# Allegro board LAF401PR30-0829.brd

Outline 328.05 x 120.8 mm; copper layers: TOP, GND1, IN1, GND2, IN2, IN3, VCC, IN4, GND3, BOTTOM. Coordinates in mm from the lower left corner of the outline.

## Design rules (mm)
net group 12: nets H_THERMTRIP# H_VCCST_PWRGD_XDP
net group 15: nets DDR_XDP_WAN_SMBDAT ESPI_CLK_5105
net group CLK_ITPXDP_: nets CLK_ITPXDP_N CLK_ITPXDP_P
net group CPU_DP2_0_C: nets CPU_DP2_N0_C CPU_DP2_P0_C
net group CPU_DP2_1_C: nets CPU_DP2_N1_C CPU_DP2_P1_C
net group CPU_DP2_2_C: nets CPU_DP2_N2_C CPU_DP2_P2_C
net group CPU_DP2_3_C: nets CPU_DP2_N3_C CPU_DP2_P3_C
net group CPU_DP2_AUX_C: nets CPU_DP2_AUXN_C CPU_DP2_AUXP_C
net group CPU_DP3_AUX: nets CPU_DP3_AUXN CPU_DP3_AUXP
net group CRT_CTL_5_10: nets CLK_DDC2_CRT DAT_DDC2_CRT
net group DDR_A_0: nets DDR_A_DQS0 DDR_A_DQS#0
net group DDR_A_1: nets DDR_A_DQS1 DDR_A_DQS#1
net group DDR_A_2: nets DDR_A_DQS2 DDR_A_DQS#2
net group DDR_A_3: nets DDR_A_DQS3 DDR_A_DQS#3
net group DDR_A_4: nets DDR_A_DQS4 DDR_A_DQS#4
net group DDR_A_5: nets DDR_A_DQS5 DDR_A_DQS#5
net group DDR_A_6: nets DDR_A_DQS6 DDR_A_DQS#6
net group DDR_A_7: nets DDR_A_DQS7 DDR_A_DQS#7
net group DDR_A_CLK0: nets DDR_A_CLK0 DDR_A_CLK#0
net group DDR_A_CLK1: nets DDR_A_CLK1 DDR_A_CLK#1
net group DDR_B_0: nets DDR_B_DQS0 DDR_B_DQS#0
net group DDR_B_1: nets DDR_B_DQS1 DDR_B_DQS#1
net group DDR_B_2: nets DDR_B_DQS2 DDR_B_DQS#2
net group DDR_B_3: nets DDR_B_DQS3 DDR_B_DQS#3
net group DDR_B_4: nets DDR_B_DQS4 DDR_B_DQS#4
net group DDR_B_5: nets DDR_B_DQS5 DDR_B_DQS#5
net group DDR_B_6: nets DDR_B_DQS6 DDR_B_DQS#6
net group DDR_B_7: nets DDR_B_DQS7 DDR_B_DQS#7
net group DDR_B_CLK0: nets DDR_B_CLK0 DDR_B_CLK#0
net group DDR_B_CLK1: nets DDR_B_CLK1 DDR_B_CLK#1
net group DIFFPAIR0: nets SML0_SMBCLK SML0_SMBDATA
net group DIFFPAIR2: nets CLK_TP_SIO_I2C_DAT DAT_TP_SIO_I2C_CLK
net group DIFFPAIR3: nets I2C1_SCK_TP I2C1_SDA_TP
net group DIFFPAIR4: nets I2C1_SCK_TP_R I2C1_SDA_TP_R
net group DIFFPAIR5: nets CLK_TP_SIO_R DAT_TP_SIO_R
net group DIFFPAIR12: nets ISH_I2C2_SCL_R ISH_I2C2_SDA_R
net group DIFFPAIR13: nets ISH_I2C2_SCL ISH_I2C2_SDA
net group DIFFPAIR14: nets ISPSCL ISPSDA
net group DIFFPAIR18: nets PCH_CL_CLK1 PCH_CL_DATA1
net group DIFFPAIR19: nets UIM_CLK UIM_DATA
net group DIFFPAIR21: nets MUX1_DP_SEL MUX1_USB_SEL
net group DIFFPAIR22: nets UPD1_SMBCLK_Q UPD1_SMBDAT_Q
net group DIFFPAIR31: nets UPD1_SMBCLK UPD1_SMBDAT
net group DIFFPAIR36: nets VCCIO_SENSE VSSIO_SENSE
net group DIFFPAIR37: nets UPD2_SMBCLK UPD2_SMBDAT
net group DIFFPAIR45: nets TUSB546A_SBU1_R TUSB546A_SBU2_R
net group DIFFPAIR46: nets TBTA_SBU1_R TBTA_SBU2_R
net group DIFFPAIR49: nets VCCSENSE VSSSENSE
net group DIFFPAIR50: nets VCC_GT_SENSE VSS_GT_SENSE
net group DP: nets CPU_DP1_AUXN CPU_DP1_AUXP
net group EDP_AUX_C: nets EDP_AUXN_C EDP_AUXP_C
net group EDP_TX0_C: nets EDP_TXN0_C EDP_TXP0_C
net group EDP_TX1_C: nets EDP_TXN1_C EDP_TXP1_C
net group HDA: nets HDA_BIT_CLK HDA_BIT_CLK_R
net group HDMI: nets CPU_DP2_CTRL_CLK CPU_DP2_CTRL_DATA
net group HDMI-CTL: nets HDMI_CTRL_CLK HDMI_CTRL_DATA
net group HDMI_CLK: nets HDMI_CLKN HDMI_CLKP
net group HDMI_L_CLK: nets HDMI_L_CLKN HDMI_L_CLKP
net group HDMI_L_TX_0: nets HDMI_L_TX_N0 HDMI_L_TX_P0
net group HDMI_L_TX_1: nets HDMI_L_TX_N1 HDMI_L_TX_P1
net group HDMI_L_TX_2: nets HDMI_L_TX_N2 HDMI_L_TX_P2
net group HDMI_TX_0: nets HDMI_TX_N0 HDMI_TX_P0
net group HDMI_TX_1: nets HDMI_TX_N1 HDMI_TX_P1
net group HDMI_TX_2: nets HDMI_TX_N2 HDMI_TX_P2
net group LAN_MDI0: nets LAN_MDIN0 LAN_MDIP0
net group LAN_MDI0_L: nets LAN_MDIN0_L LAN_MDIP0_L
net group LAN_MDI1: nets LAN_MDIN1 LAN_MDIP1
net group LAN_MDI1_L: nets LAN_MDIN1_L LAN_MDIP1_L
net group LAN_MDI2: nets LAN_MDIN2 LAN_MDIP2
net group LAN_MDI2_L: nets LAN_MDIN2_L LAN_MDIP2_L
net group LAN_MDI3: nets LAN_MDIN3 LAN_MDIP3
net group LAN_MDI3_L: nets LAN_MDIN3_L LAN_MDIP3_L
net group PCIE_PRX_C_DTX_4: nets PCIE_PRX_C_DTX_N4 PCIE_PRX_C_DTX_P4
net group PCIE_PRX_DTX_4: nets PCIE_PRX_DTX_N4 PCIE_PRX_DTX_P4
net group PCIE_PTX_C_DRX_4: nets PCIE_PTX_C_DRX_N4 PCIE_PTX_C_DRX_P4
net group PCIE_PTX_DRX_4: nets PCIE_PTX_DRX_N4 PCIE_PTX_DRX_P4
net group PCIE_RCOMP: nets PCIE_RCOMPN PCIE_RCOMPP
net group REM_DIODE1_: nets REM_DIODE1_N REM_DIODE1_P
net group REM_DIODE2_: nets REM_DIODE2_N REM_DIODE2_P
net group REM_DIODE4_: nets REM_DIODE4_N REM_DIODE4_P
net group RJ45_MDI0: nets RJ45_MDIN0 RJ45_MDIP0
net group RJ45_MDI1: nets RJ45_MDIN1 RJ45_MDIP1
net group RJ45_MDI2: nets RJ45_MDIN2 RJ45_MDIP2
net group RJ45_MDI3: nets RJ45_MDIN3 RJ45_MDIP3
net group SD/MMCDAT1/RCLK-: nets SD/MMCDAT0/RCLK+ SD/MMCDAT1/RCLK-
net group SD/MMCDAT1/RCLK-_R: nets SD/MMCDAT0/RCLK+_R SD/MMCDAT1/RCLK-_R
net group SD_UHS2_D0: nets SD_UHS2_D0N SD_UHS2_D0P
net group SD_UHS2_D1: nets SD_UHS2_D1N SD_UHS2_D1P
net group SW2_DP1_0_C: nets SW2_DP1_N0_C SW2_DP1_P0_C
net group SW2_DP1_1_C: nets SW2_DP1_N1_C SW2_DP1_P1_C
net group SW2_DP1_2_C: nets SW2_DP1_N2_C SW2_DP1_P2_C
net group SW2_DP1_3_C: nets SW2_DP1_N3_C SW2_DP1_P3_C
net group SW2_DP1_AUX_C: nets SW2_DP1_AUXN_C SW2_DP1_AUXP_C
net group SW2_DP3_0_C: nets SW2_DP3_N0_C SW2_DP3_P0_C
net group SW2_DP3_1_C: nets SW2_DP3_N1_C SW2_DP3_P1_C
net group SW2_DP3_AUX_C: nets SW2_DP3_AUXN_C SW2_DP3_AUXP_C
net group TBTA_SBU: nets TBTA_SBU1 TBTA_SBU2
net group THERMAL: nets POWER_SW#_MB POWER_SW_IN#
net group USB3_PRX_C_RD_DTX_6: nets USB3_PRX_C_RD_DTX_N6 USB3_PRX_C_RD_DTX_P6
net group USB3_PRX_L_DTX_2: nets USB3_PRX_L_DTX_N2 USB3_PRX_L_DTX_P2
net group USB3_PRX_RD_DTX_6: nets USB3_PRX_RD_DTX_N6 USB3_PRX_RD_DTX_P6
net group USB3_PTX_C_DRX_1: nets USB3_PTX_C_DRX_N1 USB3_PTX_C_DRX_P1
net group USB3_PTX_C_DRX_2: nets USB3_PTX_C_DRX_N2 USB3_PTX_C_DRX_P2
net group USB3_PTX_C_DRX_3: nets USB3_PTX_C_DRX_N3 USB3_PTX_C_DRX_P3
net group USB3_PTX_C_DRX_4: nets USB3_PTX_C_DRX_N4 USB3_PTX_C_DRX_P4
net group USB3_PTX_C_RD_DRX_6: nets USB3_PTX_C_RD_DRX_N6 USB3_PTX_C_RD_DRX_P6
net group USB3_PTX_L_DRX_2: nets USB3_PTX_L_DRX_N2 USB3_PTX_L_DRX_P2
net group USB3_PTX_RD_DRX_6: nets USB3_PTX_RD_DRX_N6 USB3_PTX_RD_DRX_P6
net group USB20_2_R: nets USB20_N2_R USB20_P2_R
net group USB20_3_R: nets USB20_N3_R USB20_P3_R
net group USB20_4_L: nets USB20_N4_L USB20_P4_L
net group USB20_5_R: nets USB20_N5_R USB20_P5_R
net group USB20_7_L: nets USB20_N7_L USB20_P7_L
net group USB20_8_R: nets USB20_N8_R USB20_P8_R
net group 20: nets +DDR_VREF_A_DQ +DDR_VREF_B_CA +DDR_VREF_B_DQ +DDR_VREF_CA DDR_DRAMRST# DDR_DRAMRST#_R INT_SPK_L+ INT_SPK_L- INT_SPK_R+ INT_SPK_R- INT_SPKR_L+ INT_SPKR_L- INT_SPKR_R+ INT_SPKR_R- SYS_RESET#
net group 5225: nets CAM_MIC_CBL_DET# CLK_ITPXDP_N_R CLK_ITPXDP_P_R CLK_PCIE_N0 CLK_PCIE_N1 CLK_PCIE_N3 CLK_PCIE_N4 CLK_PCIE_N5 CLK_PCIE_P0 CLK_PCIE_P1 CLK_PCIE_P3 CLK_PCIE_P4 CLK_PCIE_P5 CPU_DP1_CTRL_CLK CPU_DP1_CTRL_DATA CPU_DP1_N0 CPU_DP1_N1 CPU_DP1_N2 CPU_DP1_N3 CPU_DP1_P0 CPU_DP1_P1 CPU_DP1_P2 CPU_DP1_P3 CPU_DP2_AUXN CPU_DP2_AUXP CPU_DP2_N0 CPU_DP2_N1 CPU_DP2_N2 CPU_DP2_N3 CPU_DP2_P0 CPU_DP2_P1 CPU_DP2_P2 CPU_DP2_P3 EDP_AUXN EDP_AUXP EDP_BIA_PWM EDP_HPD EDP_TXN0 EDP_TXN1 EDP_TXP0 EDP_TXP1 ENVDD_PCH LPSS_UART2_RXD LPSS_UART2_TXD PANEL_BKLEN PCIE_PRX_DTX_N1 PCIE_PRX_DTX_N3 PCIE_PRX_DTX_N11 PCIE_PRX_DTX_N12 PCIE_PRX_DTX_P1 PCIE_PRX_DTX_P3 PCIE_PRX_DTX_P11 PCIE_PRX_DTX_P12 PCIE_PRX_RD_DTX_N11 PCIE_PRX_RD_DTX_N12 PCIE_PRX_RD_DTX_P11 PCIE_PRX_RD_DTX_P12 PCIE_PTX_DRX_N1 PCIE_PTX_DRX_N3 PCIE_PTX_DRX_N8 PCIE_PTX_DRX_N11 PCIE_PTX_DRX_N12 PCIE_PTX_DRX_P1 PCIE_PTX_DRX_P3 PCIE_PTX_DRX_P8 PCIE_PTX_DRX_P11 PCIE_PTX_DRX_P12 PCIE_PTX_RD_DRX_N11 PCIE_PTX_RD_DRX_P11 SATA_PRX_DTX_N0 SATA_PRX_DTX_P0 SW2_DP1_AUXN SW2_DP1_AUXP SW2_DP1_N0 SW2_DP1_N1 SW2_DP1_N2 SW2_DP1_N3 SW2_DP1_P0 SW2_DP1_P1 SW2_DP1_P2 SW2_DP1_P3 SW2_DP3_AUXN SW2_DP3_AUXP SW2_DP3_N0 SW2_DP3_N1 SW2_DP3_P0 SW2_DP3_P1 USB3_PRX_DTX_N2 USB3_PRX_DTX_N3 USB3_PRX_DTX_N4 USB3_PRX_DTX_P2 USB3_PRX_DTX_P3 USB3_PRX_DTX_P4 USB3_PTX_DRX_N1 USB3_PTX_DRX_N2 USB3_PTX_DRX_N3 USB3_PTX_DRX_N4 USB3_PTX_DRX_P1 USB3_PTX_DRX_P2 USB3_PTX_DRX_P3 USB3_PTX_DRX_P4 USB20_N2 USB20_N3 USB20_N4 USB20_N5 USB20_N7 USB20_N8 USB20_N9 USB20_N10 USB20_P2 USB20_P3 USB20_P4 USB20_P5 USB20_P7 USB20_P8 USB20_P9 USB20_P10
net group ADUIO: nets RING2 RING2_R SLEEVE SLEEVE_R
net group AUDIO: nets +LINE1-VREFO-L +LINE1-VREFO-R AUD_HP_NB_SENSE AUD_HP_OUT_L AUD_HP_OUT_L1 AUD_HP_OUT_R AUD_HP_OUT_R1 AUD_SENSE_A HP_OUT_L HP_OUT_R LINE1_L LINE1_R
net group B+: nets +PWR_SRC
net group CARD_READER: nets SD/MMCCD# SD/MMCCLK SD/MMCCLK_R SD/MMCCMD SD/MMCCMD_R SD/MMCDAT2 SD/MMCDAT2_R SD/MMCDAT3 SD/MMCDAT3_R SD_GPIO SDWP SDWP_Q
net group CLK: nets CLKREQ_PCIE#0 CLKREQ_PCIE#1 CLKREQ_PCIE#3 CLKREQ_PCIE#4 CLKREQ_PCIE#5 CPU_XDP_TCLK JTAG_CLK MEC_XTAL1 MEC_XTAL2 MEC_XTAL2_R MSCLK PCH_JTAG_TCK PCI_CLK_LPC1 SUSCLK SUSCLK_R WIGIG_32KHZ XDP_JTAGX XTALI XTALO XTALO_R
net group CPU: nets H_CATERR# PCH_PLTRST# PCH_PLTRST#_5105 PCH_PLTRST#_AND PCH_PLTRST#_EC PLTRST_LAN# PLTRST_TPM# VCCST_PWRGD XDP_OBS0 XDP_OBS0_R XDP_OBS1 XDP_OBS1_R
net group CRITICAL: nets INTRUDER# PCH_DPWROK PCH_PCIE_WAKE# PCH_RSMRST# PCIE_WAKE# PCIE_WAKE#_R RESET_OUT#_R SIO_PWRBTN# SRTCRST# SYS_RESET#_R
net group CRT_DAC_20_30: nets BLUE BLUE_CRT GREEN GREEN_CRT RED RED_CRT
net group CRT_SYNC_12_20: nets HSYNC_CONN HSYNC_CRT VSYNC_CONN VSYNC_CRT
net group CTL-LINK: nets PCH_CL_RST1#
net group DDRADD_ALERT_10/11_19/20_25: nets DDR_A_ACT# DDR_A_ALERT# DDR_A_BA0 DDR_A_BA1 DDR_A_BG0 DDR_A_BG1 DDR_A_MA0 DDR_A_MA1 DDR_A_MA2 DDR_A_MA3 DDR_A_MA4 DDR_A_MA5 DDR_A_MA6 DDR_A_MA7 DDR_A_MA8 DDR_A_MA9 DDR_A_MA10 DDR_A_MA11 DDR_A_MA12 DDR_A_MA13 DDR_A_MA14 DDR_A_MA15 DDR_A_MA16 DDR_A_PARITY DDR_B_ACT# DDR_B_ALERT# DDR_B_BA0 DDR_B_BA1 DDR_B_BG0 DDR_B_BG1 DDR_B_MA0 DDR_B_MA1 DDR_B_MA2 DDR_B_MA3 DDR_B_MA4 DDR_B_MA5 DDR_B_MA6 DDR_B_MA7 DDR_B_MA8 DDR_B_MA9 DDR_B_MA10 DDR_B_MA11 DDR_B_MA12 DDR_B_MA13 DDR_B_MA14 DDR_B_MA15 DDR_B_MA16 DDR_B_PARITY
net group DDRCTL_CKE_10/11_19/20_25: nets DDR_A_CKE0 DDR_A_CKE1 DDR_A_CS#0 DDR_A_CS#1 DDR_A_ODT0 DDR_A_ODT1 DDR_B_CKE0 DDR_B_CKE1 DDR_B_CS#0 DDR_B_CS#1 DDR_B_ODT0 DDR_B_ODT1
net group DDRD0_19/8.5/10_19/20_25: nets DDR_A_D0 DDR_A_D1 DDR_A_D2 DDR_A_D3 DDR_A_D4 DDR_A_D5 DDR_A_D6 DDR_A_D7 DDR_A_D16 DDR_A_D17 DDR_A_D18 DDR_A_D19 DDR_A_D20 DDR_A_D21 DDR_A_D22 DDR_A_D23 DDR_A_D32 DDR_A_D33 DDR_A_D34 DDR_A_D35 DDR_A_D36 DDR_A_D37 DDR_A_D38 DDR_A_D39 DDR_A_D48 DDR_A_D49 DDR_A_D50 DDR_A_D51 DDR_A_D52 DDR_A_D53 DDR_A_D54 DDR_A_D55 DDR_B_D0 DDR_B_D1 DDR_B_D2 DDR_B_D3 DDR_B_D4 DDR_B_D5 DDR_B_D6 DDR_B_D7 DDR_B_D16 DDR_B_D17 DDR_B_D18 DDR_B_D19 DDR_B_D20 DDR_B_D21 DDR_B_D22 DDR_B_D23 DDR_B_D32 DDR_B_D33 DDR_B_D34 DDR_B_D35 DDR_B_D36 DDR_B_D37 DDR_B_D38 DDR_B_D39 DDR_B_D48 DDR_B_D49 DDR_B_D50 DDR_B_D51 DDR_B_D52 DDR_B_D53 DDR_B_D54 DDR_B_D55
net group DDRD1_19/8.5/10_19/20_25: nets DDR_A_D8 DDR_A_D9 DDR_A_D10 DDR_A_D11 DDR_A_D12 DDR_A_D13 DDR_A_D14 DDR_A_D15 DDR_A_D24 DDR_A_D25 DDR_A_D26 DDR_A_D27 DDR_A_D28 DDR_A_D29 DDR_A_D30 DDR_A_D31 DDR_A_D40 DDR_A_D41 DDR_A_D42 DDR_A_D43 DDR_A_D44 DDR_A_D45 DDR_A_D46 DDR_A_D47 DDR_A_D56 DDR_A_D57 DDR_A_D58 DDR_A_D59 DDR_A_D60 DDR_A_D61 DDR_A_D62 DDR_A_D63 DDR_B_D8 DDR_B_D9 DDR_B_D10 DDR_B_D11 DDR_B_D12 DDR_B_D13 DDR_B_D14 DDR_B_D15 DDR_B_D24 DDR_B_D25 DDR_B_D26 DDR_B_D27 DDR_B_D28 DDR_B_D29 DDR_B_D30 DDR_B_D31 DDR_B_D40 DDR_B_D41 DDR_B_D42 DDR_B_D43 DDR_B_D44 DDR_B_D45 DDR_B_D46 DDR_B_D47 DDR_B_D56 DDR_B_D57 DDR_B_D58 DDR_B_D59 DDR_B_D60 DDR_B_D61 DDR_B_D62 DDR_B_D63
net group DIFFPAIR1: nets SML1_SMBCLK
net group DIFFPAIR8: nets DDR_XDP_WAN_SMBCLK
net group DIFFPAIR15: nets MEM_SMBCLK
net group DIFFPAIR16: nets PBAT_CHARGER_SMBCLK
net group DIFFPAIR17: nets PBAT_SMBCLK_C
net group DMIC: nets DMIC0 DMIC_CLK0 DMIC_CLK_CODEC
net group ESPI: nets ESPI_CS# ESPI_IO0 ESPI_IO0_R ESPI_IO1 ESPI_IO1_R ESPI_IO2 ESPI_IO2_R ESPI_IO3 ESPI_IO3_R
net group HDA_5_15: nets HDA_RST# HDA_RST#_R HDA_SDIN0 HDA_SDIN0_R HDA_SDOUT HDA_SDOUT_R HDA_SYNC HDA_SYNC_R
net group PCIE: nets PCIE_PRX_C_DTX_N1 PCIE_PRX_C_DTX_N11 PCIE_PRX_C_DTX_N12 PCIE_PRX_C_DTX_P1 PCIE_PRX_C_DTX_P11 PCIE_PRX_C_DTX_P12 PCIE_PRX_C_RD_DTX_N8 PCIE_PRX_C_RD_DTX_N11 PCIE_PRX_C_RD_DTX_N12 PCIE_PRX_C_RD_DTX_P8 PCIE_PRX_C_RD_DTX_P11 PCIE_PRX_C_RD_DTX_P12 PCIE_PRX_DTX_N8 PCIE_PRX_DTX_P8 PCIE_PRX_RD_DTX_N8 PCIE_PRX_RD_DTX_P8 PCIE_PTX_C_DRX_N1 PCIE_PTX_C_DRX_N3 PCIE_PTX_C_DRX_N8 PCIE_PTX_C_DRX_N11 PCIE_PTX_C_DRX_N12 PCIE_PTX_C_DRX_P1 PCIE_PTX_C_DRX_P3 PCIE_PTX_C_DRX_P8 PCIE_PTX_C_DRX_P11 PCIE_PTX_C_DRX_P12 PCIE_PTX_C_RD_DRX_N8 PCIE_PTX_C_RD_DRX_N11 PCIE_PTX_C_RD_DRX_N12 PCIE_PTX_C_RD_DRX_P8 PCIE_PTX_C_RD_DRX_P11 PCIE_PTX_C_RD_DRX_P12 PCIE_PTX_RD_DRX_N8 PCIE_PTX_RD_DRX_N12 PCIE_PTX_RD_DRX_P8 PCIE_PTX_RD_DRX_P12
net group POWER: nets +1.2V_MEM
net group RCOMP: nets CFG_RCOMP CPU_POPIRCOMP EDP_COMP EDRAM_OPIO_RCOMP EMMC_RCOMP EOPIO_RCOMP PCH_POPIRCOMP SD_RCOMP SM_RCOMP0 SM_RCOMP1 SM_RCOMP2 USBCOMP
net group RTC: nets PCH_RTCRST# PCH_RTCX1 PCH_RTCX2 PCH_RTCX2_R
net group SATA: nets SATA_PRX_C_DTX_N0 SATA_PRX_C_DTX_P0 SATA_PRX_C_RD_DTX_N0 SATA_PRX_C_RD_DTX_P0 SATA_PRX_RD_DTX_N0 SATA_PRX_RD_DTX_P0 SATA_PTX_C_DRX_N0 SATA_PTX_C_DRX_P0 SATA_PTX_C_RD_DRX_N0 SATA_PTX_C_RD_DRX_P0 SATA_PTX_DRX_N0 SATA_PTX_DRX_P0 SATA_PTX_RD_DRX_N0 SATA_PTX_RD_DRX_P0
net group SMBUS: nets GPP_C5 MEM_SMBDATA PBAT_CHARGER_SMBDAT PBAT_SMBDAT_C PCH_SMB_ALERT# SML1_SMBDATA
net group SPI: nets PCH_SPI_CLK PCH_SPI_CLK_0_R PCH_SPI_CLK_1_R PCH_SPI_CLK_2_R PCH_SPI_CLK_R1 PCH_SPI_CS#0 PCH_SPI_CS#0_R1 PCH_SPI_CS#0_R2 PCH_SPI_CS#1 PCH_SPI_CS#1_R1 PCH_SPI_CS#1_R2 PCH_SPI_CS#2 PCH_SPI_CS#2_R PCH_SPI_D0 PCH_SPI_D0_0_R PCH_SPI_D0_1_R PCH_SPI_D0_2_R PCH_SPI_D0_R1 PCH_SPI_D1 PCH_SPI_D1_0_R PCH_SPI_D1_1_R PCH_SPI_D1_2_R PCH_SPI_D1_R1 PCH_SPI_D2 PCH_SPI_D2_0_R PCH_SPI_D2_1_R PCH_SPI_D2_R1 PCH_SPI_D3 PCH_SPI_D3_0_R PCH_SPI_D3_1_R PCH_SPI_D3_R1 PCH_SPI_DO2_XDP PCH_SPI_DO_XDP TBTA_ROM_CLK_PD TBTA_ROM_CLK_PD_R TBTA_ROM_CS#_PD TBTA_ROM_CS#_PD_R TBTA_ROM_DI_PD TBTA_ROM_DI_PD_R TBTA_ROM_DO_PD TBTA_ROM_DO_PD_R
net group SVID: nets H_CPU_SVIDALRT# PECI_EC PECI_EC_R VIDALERT_N VIDALERT_N_B VIDSCLK VIDSCLK_B VIDSOUT VIDSOUT_B
net group TBTA-USB30: nets TBTA_AUXN_C TBTA_AUXP_C TBTA_BOT_N TBTA_BOT_N_R TBTA_BOT_P TBTA_BOT_P_R TBTA_RX1N TBTA_RX1P TBTA_RX2N TBTA_RX2P TBTA_TOP_N TBTA_TOP_N_R TBTA_TOP_P TBTA_TOP_P_R TBTA_TX1N TBTA_TX1N_C TBTA_TX1P TBTA_TX1P_C TBTA_TX2N TBTA_TX2N_C TBTA_TX2P TBTA_TX2P_C
net group UIM: nets UIM_RESET
net group USB20: nets SW_USB20_N9 SW_USB20_P9 USB20_N1 USB20_N9_R USB20_P1 USB20_P9_R
net group USB30: nets USB3_PRX_C_DTX_N1 USB3_PRX_C_DTX_P1 USB3_PRX_DTX_N1 USB3_PRX_DTX_N6 USB3_PRX_DTX_P1 USB3_PRX_DTX_P6 USB3_PTX_C_DRX_N6 USB3_PTX_C_DRX_P6 USB3_PTX_DRX_N6 USB3_PTX_DRX_P6
nets with their own width: min track width 0.254; nets +1.0VO_DSW +1.2V_MEM_CPUCLK +5V_ALW +VCC_GT_AK52 +VCC_GT_K52 AUD_PC_BEEP BAT1_LED# BAT2_LED# BATT_WHITE# BATT_YELLOW# BEEP_R N16400770 N18762401 N18762411 N18762416 N18762426 N18762428 N18762438 N20151644 N27077001 N132005053 SLP_WLAN#_M SPKR_R TBTA_CC1 VCC_GT VCC_IA1 VCC_IA2 WLAN_PWR_EN XCLK_BIASREF
nets with their own width: min track width 0.305; nets +RREF
nets with their own width: min track width 0.508; nets +1.0V_AMPHYPLL +1.0V_APLL +1.0V_APLLEBB +1.0V_CLK1 +1.0V_CLK2 +1.0V_CLK3 +1.0V_CLK4 +1.0V_CLK5 +1.0V_CLK6 +1.0V_DTS +1.0V_PRIM +1.0V_PRIM_XDP +1.0V_VCCST +1.0V_VCCST_C +1.0V_VCCSTG +1.0V_VCCSTG_C +1.2V_LDO +1.8V_PRIM +1.8V_RUN +1.8V_RUN_CARD +3.3V_1.8V_PGPPA +3.3V_1.8V_PGPPG +3.3V_ALW +3.3V_ALW2 +3.3V_ALW_DSW +3.3V_ALW_DSW_R +3.3V_ALW_PCH +3.3V_ALW_UE1 +3.3V_ALW_UZ12 +3.3V_CAM +3.3V_CPS +3.3V_LAN_OUT +3.3V_M_TPM +3.3V_MMI_AUX +3.3V_PGPPB +3.3V_PGPPC +3.3V_PGPPD +3.3V_PGPPE +3.3V_RTC_LDO +3.3V_RUN +3.3V_RUN_AUDIO +3.3V_RUN_AUDIO_DVDD +3.3V_RUN_AUDIO_IO +3.3V_RUN_AUDIO_UZ5 +3.3V_RUN_UT9 +3.3V_SPI +3.3V_TBTA_FLASH +3.3V_TP +3.3V_VCCHDA +5V_ALW2 +5V_RUN +5V_RUN_CHG +COINCELL +DC_IN_SS +DDR_VREF_A_CA +DV33_18 +GND_CHASSIS +MIC2-VREFO +RSVD_VCC3P3_1 +RTC_CELL +RTC_CELL_PCH +SDREG2 +UZ12_TPM +UZ12_VHIO +VBUS_DC_SS +VCC_1P8 +VCC_CORE +VCC_GT +VCC_SA +VCC_SFR_OC +VDD_DAC_33 +VDDA_AVDD1 +VSS_PLL +Z4012 GND GNDA GT_SNUB IA_SNUB1 IA_SW1
nets with their own width: min track width 0.762; nets +0.9V_LAN +1.0V_SRAM +2.5V_MEM +3.3V_VDD_PIC +3.3V_VDD_PIC_PDA +3.3V_VGA
nets with their own width: min track width 1.016; nets +0.6V_DDR_VTT +1.8V_PGPPF +1.8V_RUN_UZ8 +3.3V_ALW_PCH_UZ3 +3.3V_LAN +3.3V_LAN_UZ2 +3.3V_RUN_CARD +5V_TSP +CRT_VCC +VHDMI_VCC
nets with their own width: min track width 1.27; nets +3.3V_MMI_IN
nets with their own width: min track width 1.524; nets +5V_HDD +5V_HDD_UZ23 +EDP_VDD +LCDVDD
nets with their own width: min track width 2.032; nets +BL_PWR_SRC +USB_EX2_PWR +USB_EX3_PWR
nets with their own width: min track width 2.286; nets +3.3V_HDD +3.3V_WLAN +3.3V_WWAN_UZ2
nets with their own width: min track width 2.54; nets +5V_RUN_AUDIO +5V_RUN_AUDIO_UZ5 +5V_RUN_PVDD_L +5V_RUN_UZ4 +5V_USB_CHG_PWR
nets with their own width: min track width 2.794; nets +1.0V_PRIM_CORE +3.3V_WLAN_UZ4 +3.3V_WWAN
nets with their own width: min track width 3.048; nets +1.0V_MPHYAON +1.0V_MPHYGT +3.3V_HDD_M2
nets with their own width: min track width 3.302; nets +1.0VS_VCCIO
nets with their own width: min track width 3.556; nets +3.3V_RUN_UZ3 +5V_ALW_PDA

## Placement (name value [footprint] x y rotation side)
CA1  680P_0402_50V7K  [C_0402]  313.82 40.29 270 bottom
CA2  330P_0402_50V8J  [C_0402]  312.62 33.55 270 top
CA3  330P_0402_50V8J  [C_0402]  311.54 34.82 270 bottom
CA4  680P_0402_50V7K  [C_0402]  311.97 40.28 0 bottom
CA5  100P_0402_50V8J  [C_0402]  113.67 88.8 270 bottom
CA6  100P_0402_50V8J  [C_0402]  114.69 88.8 270 bottom
CA7  100P_0201_25V7K  [C_0201]  111.89 91.84 0 top
CA8  0.1U_0201_10V6K  [C_0201]  304.04 33.2 270 top
CA9  10U_0603_10V6M  [C_0603]  305.63 31.7 180 top
CA10  0.1U_0201_10V6K  [C_0201]  295.28 38.33 90 top
CA12  680P_0402_50V7K  [C_0402]  312.3 36.67 270 bottom
CA13  680P_0402_50V7K  [C_0402]  310.65 41.17 270 bottom
CA19  1000P_0402_50V7K  [C_0402]  297.69 39.21 270 bottom
CA22  1000P_0402_50V7K  [C_0402]  300.36 39.21 270 bottom
CA23  1000P_0402_50V7K  [C_0402]  299.47 39.21 270 bottom
CA24  1000P_0402_50V7K  [C_0402]  298.58 39.21 270 bottom
CA25  10U_0603_10V6M  [C_0603]  300.55 29.42 0 top
CA27  0.1U_0402_25V6  [C_0402]  299.65 29.93 180 top
CA28  0.1U_0402_25V6  [C_0402]  296.85 29.93 0 top
CA29  1U_0603_10V6K  [C_0603]  304.17 38.69 90 top
CA31  1U_0603_10V6K  [C_0603]  296.8 39.9 180 top
CA33  10P_0402_50V8J  [C_0402]  291.75 37.1 180 top
CA35  2.2U_0402_6.3V6M  [C_0402]  306.76 34.31 0 top
CA41  0.1U_0402_25V6  [C_0402]  295.34 30.83 270 top
CA43  10U_0603_10V6M  [C_0603]  305.63 30.12 0 top
CA44  10U_0603_10V6M  [C_0603]  303.28 30.12 0 top
CA45  0.1U_0201_10V6K  [C_0201]  300.14 41.29 180 top
CA46  10U_0603_10V6M  [C_0603]  300.23 42.18 180 top
CA47  0.1U_0201_10V6K  [C_0201]  298.04 41.29 0 top
CA48  10U_0603_10V6M  [C_0603]  298.84 44.73 180 top
CA49  1U_0603_10V6K  [C_0603]  305.44 38.69 90 top
CA51  10U_0603_10V6M  [C_0603]  306.58 33.23 0 top
CA52  10U_0603_10V6M  [C_0603]  304.17 41.1 90 top
CA53  10U_0603_10V6M  [C_0603]  294.14 36.02 180 top
CA54  27P_0402_50V8J  [C_0402]  291.75 37.99 180 top
CA55  0.1U_0201_10V6K  [C_0201]  295.28 33.77 270 top
CA56  10U_0603_10V6M  [C_0603]  294.52 33.8 180 top
CA57  0.1U_0201_10V6K  [C_0201]  301.4 40.21 0 top
CA58  10U_0603_10V6M  [C_0603]  301.44 41.42 0 top
CA59  10U_0603_10V6M  [C_0603]  310.08 27.89 0 top
CA60  0.1U_0201_10V6K  [C_0201]  306.84 27.67 90 top
CA61  10U_0603_10V6M  [C_0603]  293.76 39.92 180 top
CA62  100P_0402_50V8J  [C_0402]  296.8 29.05 270 top
CA63  12P_0402_50V8J  [C_0402]  276.74 68.29 270 top
CA64  68P_0402_50V8J  [C_0402]  275.72 68.29 270 top
CA65  12P_0402_50V8J  [C_0402]  272.62 45.99 180 top
CA66  68P_0402_50V8J  [C_0402]  272.62 45.1 180 top
CA67  12P_0402_50V8J  [C_0402]  272.42 78.5 90 top
CA68  68P_0402_50V8J  [C_0402]  271.53 78.5 90 top
CA69  33P_0402_50V8J  [C_0402]  302.27 37.31 270 bottom
CA72  100P_0402_50V8J  [C_0402]  299.6 28.67 270 top
CC7  33P_0402_50V8J  [C_0402]  150.42 53.83 0 bottom
CC8  33P_0402_50V8J  [C_0402]  151.14 63.95 90 bottom
CC9  0.1U_0201_10V6K  [C_0201]  152.02 66.95 270 bottom
CC10  0.1U_0201_10V6K  [C_0201]  151.14 58.57 180 bottom
CC21  12P_0402_50V8J  [C_0402]  116.6 80.27 180 bottom
CC22  12P_0402_50V8J  [C_0402]  117.47 80.27 0 bottom
CC23  12P_0402_50V8J  [C_0402]  149.61 42.18 180 bottom
CC26  12P_0402_50V8J  [C_0402]  152.41 43.58 180 bottom
CC27  47P_0402_50V8J  [C_0402]  127.02 35.51 180 top
CC28  0.1U_0201_10V6K  [C_0201]  64.9 27.68 270 top
CC29  0.1U_0201_10V6K  [C_0201]  64.14 38.52 90 top
CC30  0.1U_0201_10V6K  [C_0201]  56.01 32.25 270 top
CC32  0.1U_0402_25V6  [C_0402]  63.89 27.59 270 top
CC33  0.1U_0402_25V6  [C_0402]  62.36 38.36 90 top
CC78  1U_0201_6.3V6M  [C_0201]  135.06 39.78 270 top
CC79  1U_0201_6.3V6M  [C_0201]  134.45 39.78 270 top
CC80  1U_0201_6.3V6M  [C_0201]  153.93 52.36 270 bottom
CC81  1U_0201_6.3V6M  [C_0201]  153.34 52.36 270 bottom
CC84  1U_0201_6.3V6M  [C_0201]  121.15 64.92 180 top
CC85  1U_0201_6.3V6M  [C_0201]  121.15 65.5 180 top
CC86  1U_0201_6.3V6M  [C_0201]  128.95 64.74 180 top
CC87  1U_0201_6.3V6M  [C_0201]  128.43 64.14 270 top
CC88  1U_0201_6.3V6M  [C_0201]  131.98 54.11 270 top
CC89  1U_0201_6.3V6M  [C_0201]  133.16 53.76 180 top
CC90  1U_0201_6.3V6M  [C_0201]  126.89 56.86 180 top
CC91  1U_0201_6.3V6M  [C_0201]  126.89 57.45 180 top
CC92  1U_0201_6.3V6M  [C_0201]  128.39 61 0 top
CC93  1U_0201_6.3V6M  [C_0201]  128.39 61.59 0 top
CC94  1U_0201_6.3V6M  [C_0201]  128.64 58.31 180 top
CC95  1U_0201_6.3V6M  [C_0201]  128.64 57.73 180 top
CC96  1U_0201_6.3V6M  [C_0201]  127.45 59.12 180 top
CC97  1U_0201_6.3V6M  [C_0201]  127.45 58.54 180 top
CC98  1U_0201_6.3V6M  [C_0201]  156.2 67.43 0 top
CC99  1U_0201_6.3V6M  [C_0201]  156.2 66.85 0 top
CC100  1U_0201_6.3V6M  [C_0201]  148.4 60.7 0 top
CC101  1U_0201_6.3V6M  [C_0201]  148.4 60.09 0 top
CC102  1U_0201_6.3V6M  [C_0201]  127.02 55.16 0 top
CC103  1U_0201_6.3V6M  [C_0201]  127.02 55.75 0 top
CC104  1U_0201_6.3V6M  [C_0201]  127.89 33.3 270 top
CC105  1U_0201_6.3V6M  [C_0201]  127.32 33.3 270 top
CC106  1U_0201_6.3V6M  [C_0201]  137.69 84.3 0 top
CC107  1U_0201_6.3V6M  [C_0201]  137.69 84.93 0 top
CC108  1U_0201_6.3V6M  [C_0201]  125.47 58.23 180 top
CC109  1U_0201_6.3V6M  [C_0201]  125.47 57.65 180 top
CC110  1U_0201_6.3V6M  [C_0201]  144.84 74.02 90 top
CC111  1U_0201_6.3V6M  [C_0201]  144.25 74.02 90 top
CC112  1U_0201_6.3V6M  [C_0201]  130.14 59.57 0 top
CC113  1U_0201_6.3V6M  [C_0201]  129.48 59.57 180 top
CC118  1U_0201_6.3V6M  [C_0201]  120.06 55.89 90 top
CC119  1U_0201_6.3V6M  [C_0201]  119.49 55.89 90 top
CC122  1U_0201_6.3V6M  [C_0201]  118.23 53.43 180 top
CC123  1U_0201_6.3V6M  [C_0201]  118.23 54.04 180 top
CC124  1U_0201_6.3V6M  [C_0201]  128.9 56.61 180 top
CC125  1U_0201_6.3V6M  [C_0201]  128.9 56.03 180 top
CC126  1U_0201_6.3V6M  [C_0201]  150.54 57.88 0 bottom
CC127  1U_0201_6.3V6M  [C_0201]  150.54 57.3 0 bottom
CC128  1U_0201_6.3V6M  [C_0201]  147.9 68.85 0 top
CC129  1U_0201_6.3V6M  [C_0201]  147.9 69.44 0 top
CC176  10U_0402_6.3V6M  [C_0402]  115.32 42.19 270 top
CC177  10U_0402_6.3V6M  [C_0402]  112.91 41.93 90 top
CC178  10U_0402_6.3V6M  [C_0402]  118.75 38.5 90 top
CC179  10U_0402_6.3V6M  [C_0402]  103.15 38.34 90 top
CC195  1U_0402_6.3V6K  [C_0402]  124.47 63.77 180 top
CC202  1U_0402_6.3V6K  [C_0402]  124.27 80.19 180 top
CC210  47U_0805_6.3V6M  [C_0805]  155.33 65.68 0 top
CC214  0.1U_0201_10V6K  [C_0201]  139.2 39.77 270 top
CC219  22U_0603_6.3V6M  [C_0603]  147.48 70.33 0 top
CC220  22U_0603_6.3V6M  [C_0603]  126.77 80.31 90 top
CC221  22U_0603_6.3V6M  [C_0603]  135.01 84.51 90 top
CC223  0.1U_0201_10V6K  [C_0201]  131.13 56.46 180 top
CC224  1U_0402_6.3V6K  [C_0402]  131.98 55.47 90 top
CC225  12P_0402_50V8J  [C_0402]  144.53 65.3 0 top
CC226  22U_0603_6.3V6M  [C_0603]  124.3 80.56 180 bottom
CC250  1U_0402_6.3V6K  [C_0402]  120.79 55.28 90 top
CC252  1U_0402_6.3V6K  [C_0402]  119 54 270 top
CC266  0.01UF_0402_25V7K  [C_0402]  130.18 36.34 270 top
CC269  0.1U_0402_25V6  [C_0402]  65.92 38.36 90 top
CC270  0.1U_0201_10V6K  [C_0201]  126.43 53.14 180 top
CC279  22U_0603_6.3V6M  [C_0603]  175.14 31.01 270 top
CC280  22U_0603_6.3V6M  [C_0603]  176.34 31.01 270 top
CC281  0.1U_0201_10V6K  [C_0201]  156.2 68.01 0 top
CC288  1U_0402_6.3V6K  [C_0402]  121.54 28.97 90 top
CC294  22U_0603_6.3V6M  [C_0603]  111 42.18 270 top
CC295  22U_0603_6.3V6M  [C_0603]  120.53 37.1 90 top
CC296  22U_0603_6.3V6M  [C_0603]  120.53 41.55 270 top
CC297  10U_0402_6.3V6M  [C_0402]  114.06 53.87 180 top
CC300  100P_0402_50V8J  [C_0402]  91.25 80.24 90 bottom
CC301  100P_0402_50V8J  [C_0402]  96.65 77.12 270 bottom
CC302  0.1U_0402_25V6  [C_0402]  147.25 87.45 0 bottom
CC303  0.1U_0402_25V6  [C_0402]  105.8 75.44 90 bottom
CC304  0.1U_0402_25V6  [C_0402]  104.02 75.46 90 bottom
CC305  0.1U_0402_25V6  [C_0402]  102.75 75.44 90 bottom
CC306  0.1U_0402_25V6  [C_0402]  54.74 35.82 90 top
CC307  0.1U_0402_25V6  [C_0402]  66.93 38.36 90 top
CC308  0.1U_0402_25V6  [C_0402]  53.22 29.3 270 top
CC310  0.1U_0402_25V6  [C_0402]  94.62 79.9 90 bottom
CC312  0.1U_0402_25V6  [C_0402]  100.72 79 90 bottom
CC313  0.1U_0201_10V6K  [C_0201]  125.5 54.69 270 top
CC314  0.1U_0201_10V6K  [C_0201]  132.63 60.47 270 top
CC316  33P_0402_50V8J  [C_0402]  139.71 42.83 270 top
CC318  33P_0402_50V8J  [C_0402]  149.23 60.22 180 bottom
CC319  33P_0402_50V8J  [C_0402]  146.61 62.76 180 bottom
CC320  33P_0402_50V8J  [C_0402]  148.67 66.12 180 top
CC321  33P_0402_50V8J  [C_0402]  100.59 75.46 90 bottom
CC322  2.2P_0402_50V8C  [C_0402]  122.43 28.97 90 top
CC323  2.2P_0402_50V8C  [C_0402]  144.45 61.31 90 top
CC324  2.2P_0402_50V8C  [C_0402]  125.35 32.53 90 top
CC325  2.2P_0402_50V8C  [C_0402]  126.44 61.51 180 top
CC331  2.2P_0402_50V8C  [C_0402]  128.02 36.39 90 top
CC332  2.2P_0402_50V8C  [C_0402]  128.41 31.64 180 top
CC333  2.2P_0402_50V8C  [C_0402]  128.94 40.12 90 top
CC334  12P_0402_50V8J  [C_0402]  145.57 72.76 0 bottom
CC335  12P_0402_50V8J  [C_0402]  145.55 75.58 90 bottom
CC336  100P_0402_50V8J  [C_0402]  96.78 78.99 90 bottom
CC337  12P_0402_50V8J  [C_0402]  125.71 59.94 270 top
CC340  0.1U_0402_25V6K  [C_0402]  177.2 33.55 180 top
CC341  18P_0402_50V8J  [C_0402]  159.57 55.44 0 top
CD1  10U_0603_10V6M  [C_0603]  65.63 13.84 270 top
CD2  10U_0603_10V6M  [C_0603]  79.34 13.59 270 top
CD3  10U_0603_10V6M  [C_0603]  74.14 4.07 90 top
CD4  10U_0603_10V6M  [C_0603]  68.29 4.07 90 top
CD5  10U_0603_10V6M  [C_0603]  52.61 4.76 0 top
CD6  10U_0603_10V6M  [C_0603]  75.41 13.59 270 top
CD7  10U_0603_10V6M  [C_0603]  71.72 4.07 90 top
CD8  10U_0603_10V6M  [C_0603]  59.95 13.86 270 top
CD17  330U_D3_2.5VY_R6M  [C_D3]  85.63 13.12 90 top
CD20  10U_0603_10V6M  [C_0603]  109.06 10.42 90 top
CD21  10U_0603_10V6M  [C_0603]  107.79 10.42 90 top
CD22  10U_0603_10V6M  [C_0603]  106.81 3.95 270 top
CD25  0.1U_0402_10V6K  [C_0402]  81.92 5.24 270 top
CD26  2.2U_0402_6.3V6M  [C_0402]  82.94 5.24 270 top
CD27  2.2U_0402_6.3V6M  [C_0402]  104.82 8.95 180 top
CD28  0.1U_0201_10V6K  [C_0201]  104.65 9.72 180 top
CD29  0.1U_0402_25V6  [C_0402]  65.88 5.27 180 top
CD31  0.022U_0402_16V7K  [C_0402]  83.75 3.25 0 top
CD32  0.1U_0201_10V6K  [C_0201]  90.52 12.56 90 top
CD33  10U_0603_10V6M  [C_0603]  155.33 15.89 270 top
CD34  10U_0603_10V6M  [C_0603]  157.61 15.89 270 top
CD35  10U_0603_10V6M  [C_0603]  147.39 15.19 180 top
CD36  10U_0603_10V6M  [C_0603]  153.8 15.89 270 top
CD37  10U_0603_10V6M  [C_0603]  170.06 12.46 90 top
CD38  10U_0603_10V6M  [C_0603]  150.5 14.49 90 top
CD39  10U_0603_10V6M  [C_0603]  140.03 13.72 270 top
CD40  10U_0603_10V6M  [C_0603]  127.33 12.32 90 top
CD49  330U_D3_2.5VY_R6M  [C_D3]  165.21 18.31 0 top
CD52  10U_0603_10V6M  [C_0603]  190.58 12.06 90 top
CD53  10U_0603_10V6M  [C_0603]  190.58 11.09 270 top
CD54  10U_0603_10V6M  [C_0603]  190.12 6.49 270 top
CD57  0.1U_0402_10V6K  [C_0402]  169.45 4.4 90 top
CD58  2.2U_0402_6.3V6M  [C_0402]  168.43 4.4 90 top
CD59  2.2U_0402_6.3V6M  [C_0402]  186.59 12.16 90 top
CD60  0.1U_0201_10V6K  [C_0201]  185.81 12.25 90 top
CD61  0.1U_0402_25V6  [C_0402]  141.46 3.76 180 top
CD62  0.022U_0402_16V7K  [C_0402]  172.22 2.29 90 top
CD64  1U_0201_6.3V6M  [C_0201]  70.31 4.86 90 top
CD65  1U_0201_6.3V6M  [C_0201]  69.73 4.86 90 top
CD66  1U_0201_6.3V6M  [C_0201]  71.58 12.86 270 top
CD67  1U_0201_6.3V6M  [C_0201]  71 12.86 270 top
CD68  1U_0201_6.3V6M  [C_0201]  86.73 6.75 0 top
CD69  1U_0201_6.3V6M  [C_0201]  86.73 7.33 0 top
CD70  1U_0201_6.3V6M  [C_0201]  62.95 4.93 90 top
CD71  1U_0201_6.3V6M  [C_0201]  62.36 4.93 90 top
CD72  1U_0201_6.3V6M  [C_0201]  57.84 14.23 270 top
CD73  1U_0201_6.3V6M  [C_0201]  58.43 14.23 270 top
CD74  1U_0201_6.3V6M  [C_0201]  48.06 12.86 270 top
CD75  1U_0201_6.3V6M  [C_0201]  47.48 12.86 270 top
CD76  1U_0201_6.3V6M  [C_0201]  106.89 11.36 90 top
CD77  1U_0201_6.3V6M  [C_0201]  106.3 11.36 90 top
CD78  1U_0201_6.3V6M  [C_0201]  105.72 11.36 90 top
CD79  1U_0201_6.3V6M  [C_0201]  108.16 9.63 270 top
CD80  1U_0201_6.3V6M  [C_0201]  107.71 5.56 0 top
CD81  1U_0201_6.3V6M  [C_0201]  107.71 6.13 0 top
CD82  1U_0201_6.3V6M  [C_0201]  107.71 4.98 0 top
CD83  1U_0201_6.3V6M  [C_0201]  107.71 4.41 0 top
CD84  1U_0201_6.3V6M  [C_0201]  166.86 8.69 270 top
CD85  1U_0201_6.3V6M  [C_0201]  166.86 6.91 90 top
CD86  1U_0201_6.3V6M  [C_0201]  171.71 13.09 90 top
CD87  1U_0201_6.3V6M  [C_0201]  171.12 13.09 90 top
CD88  1U_0201_6.3V6M  [C_0201]  181.16 11.66 90 top
CD89  1U_0201_6.3V6M  [C_0201]  180.57 11.66 90 top
CD90  1U_0201_6.3V6M  [C_0201]  135.34 4.96 90 top
CD91  1U_0201_6.3V6M  [C_0201]  134.75 4.96 90 top
CD92  1U_0201_6.3V6M  [C_0201]  126.73 4.98 90 top
CD93  1U_0201_6.3V6M  [C_0201]  126.14 4.98 90 top
CD94  1U_0201_6.3V6M  [C_0201]  128.86 12.88 90 top
CD95  1U_0201_6.3V6M  [C_0201]  128.25 12.88 90 top
CD96  1U_0201_6.3V6M  [C_0201]  139.12 12.65 270 top
CD97  1U_0201_6.3V6M  [C_0201]  138.54 12.65 270 top
CD98  1U_0201_6.3V6M  [C_0201]  177.09 4.88 90 top
CD99  1U_0201_6.3V6M  [C_0201]  176.51 4.88 90 top
CD100  1U_0201_6.3V6M  [C_0201]  189.69 12.25 90 top
CD101  1U_0201_6.3V6M  [C_0201]  189.11 12.25 90 top
CD102  1U_0201_6.3V6M  [C_0201]  189.69 10.8 270 top
CD103  1U_0201_6.3V6M  [C_0201]  189.11 10.8 270 top
CD104  1U_0201_6.3V6M  [C_0201]  189.24 5.9 270 top
CD105  1U_0201_6.3V6M  [C_0201]  188.65 5.9 270 top
CD106  1U_0201_6.3V6M  [C_0201]  188.07 5.9 270 top
CD107  1U_0201_6.3V6M  [C_0201]  187.48 5.9 270 top
CD108  1U_0201_6.3V6M  [C_0201]  102.41 9.01 180 top
CD109  1U_0201_6.3V6M  [C_0201]  102.41 9.59 180 top
CD110  1U_0201_6.3V6M  [C_0201]  70.41 12.86 270 top
CD111  1U_0201_6.3V6M  [C_0201]  69.83 12.86 270 top
CE3  2200P_0402_50V7K  [C_0402]  304.84 68.89 0 top
CE4  2200P_0402_50V7K  [C_0402]  310.25 69.49 0 top
CE8  .047U_0402_16V7K  [C_0402]  307.46 84.16 0 top
CE11  0.1U_0201_10V6K  [C_0201]  290.14 77.19 180 top
CE12  2.2U_0402_6.3V6M  [C_0402]  287.91 70.83 270 top
CE13  0.1U_0201_10V6K  [C_0201]  293.48 75.88 270 top
CE15  0.1U_0201_10V6K  [C_0201]  301.37 69.5 180 top
CE16  10U_0603_6.3V6M  [C_0603]  306.98 64.39 90 top
CE17  22U_0603_6.3V6M  [C_0603]  299.35 68.62 0 top
CE18  0.1U_0201_10V6K  [C_0201]  299.53 69.63 0 top
CE19  0.1U_0201_10V6K  [C_0201]  307.66 78.75 0 top
CE20  0.1U_0201_10V6K  [C_0201]  307.65 78.15 0 top
CE21  0.1U_0201_10V6K  [C_0201]  308.36 75.88 270 top
CE22  0.1U_0201_10V6K  [C_0201]  310.51 72.25 0 top
CE23  0.1U_0201_10V6K  [C_0201]  300.84 66.8 180 top
CE24  2200P_0402_50V7K  [C_0402]  292.93 77.63 270 top
CE25  0.1U_0201_10V6K  [C_0201]  304.63 86.89 90 top
CE26  2200P_0402_50V7K  [C_0402]  291.98 79.15 270 top
CE27  2200P_0402_50V7K  [C_0402]  292.93 80.55 270 top
CE28  10P_0402_50V8J  [C_0402]  292.63 71.16 270 top
CE29  10P_0402_50V8J  [C_0402]  292.37 72.2 90 top
CE32  10U_0603_6.3V6M  [C_0603]  266.18 39.08 180 top
CE35  100P_0402_50V8J  [C_0402]  124.12 57.66 90 top
CE36  0.1U_0402_25V6  [C_0402]  285.37 73.12 270 top
CE37  100P_0402_50V8J  [C_0402]  238.69 11.96 0 bottom
CE38  0.1U_0402_25V6  [C_0402]  293.32 81.68 180 top
CE39  100P_0402_50V8J  [C_0402]  79.14 45.61 180 top
CE40  4700P_0402_25V7K  [C_0402]  302.65 86.12 0 top
CE46  100P_0402_50V8J  [C_0402]  113.67 11.32 180 bottom
CE47  4700P_0402_25V7K  [C_0402]  301.63 88.97 90 top
CE52  0.1U_0402_25V6K  [C_0402]  305.39 91.46 180 top
CE53  0.1U_0402_25V6K  [C_0402]  308.49 92.42 270 top
CE54  10P_0402_50V8J  [C_0402]  298.07 63.85 270 top
CE57  33P_0402_50V8J  [C_0402]  284.92 79.34 0 top
CE59  12P_0402_50V8J  [C_0402]  314.9 72.2 90 top
CE60  68P_0402_50V8J  [C_0402]  313.95 72.2 90 top
CE61  68P_0402_50V8J  [C_0402]  302.9 88.04 270 top
CE62  4700P_0402_25V7K  [C_0402]  298.9 67.53 270 top
CE64  0.1U_0402_25V6  [C_0402]  286.92 76.88 270 top
CE65  22P_0402_50V8J  [C_0402]  316.69 62.82 180 top
CE66  0.1U_0402_25V6  [C_0402]  304.87 75.34 270 bottom
CE70  100P_0402_50V8J  [C_0402]  266.02 38.02 180 top
CE101  1U_0201_6.3V6M  [C_0201]  285.21 70.9 90 top
CE102  1U_0201_6.3V6M  [C_0201]  284.64 70.9 90 top
CE141  1U_0201_6.3V6M  [C_0201]  290.39 76.35 180 top
CE142  1U_0201_6.3V6M  [C_0201]  290.39 75.76 180 top
CE301  1U_0201_6.3V6M  [C_0201]  300.63 84.8 180 top
CE302  1U_0201_6.3V6M  [C_0201]  300.63 84.22 180 top
CE311  1U_0201_6.3V6M  [C_0201]  304.03 68.29 180 top
CE312  1U_0201_6.3V6M  [C_0201]  304.03 68.88 180 top
CE631  1U_0201_6.3V6M  [C_0201]  321.63 65.58 0 top
CE632  1U_0201_6.3V6M  [C_0201]  321.63 65.02 0 top
CI1  100U_1206_6.3V6M  [C_1206]  19.57 76.33 270 top
CI3  0.1U_0201_10V6K  [C_0201]  20.89 78.24 90 top
CI4  0.1U_0402_25V6  [C_0402]  21.21 72.54 0 top
CI5  0.1U_0402_25V6  [C_0402]  21.21 71.65 0 top
CI6  10U_0603_10V6M  [C_0603]  25.15 75.71 0 top
CI7  0.1U_0201_10V6K  [C_0201]  25.24 76.66 0 top
CI8  100U_1206_6.3V6M  [C_1206]  88.64 102.02 0 bottom
CI10  0.1U_0201_10V6K  [C_0201]  85.56 103.45 225 bottom
CI11  10U_0603_10V6M  [C_0603]  81.22 99.59 180 bottom
CI12  0.1U_0201_10V6K  [C_0201]  83.66 102.58 0 bottom
CI13  0.1U_0402_25V6  [C_0402]  307.68 53.61 180 top
CI14  100U_1206_6.3V6M  [C_1206]  306.58 39.13 180 bottom
CI16  0.1U_0402_25V6  [C_0402]  307.68 52.6 180 top
CI17  0.1U_0201_10V6K  [C_0201]  309.1 44.28 180 top
CI19  0.1U_0201_10V6K  [C_0201]  309.5 63.31 90 top
CI27  0.1U_0402_25V6  [C_0402]  81.67 100.55 270 top
CI28  0.1U_0402_25V6  [C_0402]  82.68 100.55 270 top
CI29  0.1U_0402_25V6  [C_0402]  294.71 48.9 90 top
CI30  0.1U_0402_25V6  [C_0402]  295.6 48.9 90 top
CI31  10U_0402_6.3V6M  [C_0402]  305.69 60.65 90 top
CI32  150U_B2_6.3VM_R35M  [C_B2-NPM]  306.62 39.07 0 bottom
CI33  47U_0603_6.3V6M  [C_0603]  305.69 58.76 270 top
CI34  47U_0603_6.3V6M  [C_0603]  310.51 63.26 0 top
CI37  0.1U_0402_16V4Z  [C_0402]  304.68 60.65 90 top
CI38  0.01UF_0402_25V7K  [C_0402]  299.22 52.67 270 top
CI39  0.1U_0402_10V7K  [C_0402]  297.77 57.68 180 top
CI40  0.1U_0402_10V7K  [C_0402]  297.77 56.66 180 top
CI41  0.1U_0402_10V7K  [C_0402]  296.85 55.64 0 top
CI42  0.1U_0402_10V7K  [C_0402]  296.85 54.63 0 top
CI43  12P_0402_50V8J  [C_0402]  310.9 46.11 90 top
CI44  68P_0402_50V8J  [C_0402]  310.01 46.11 90 top
CI45  12P_0402_50V8J  [C_0402]  20.13 78.24 90 top
CI46  68P_0402_50V8J  [C_0402]  19.24 78.24 90 top
CI47  12P_0402_50V8J  [C_0402]  87.66 103.78 0 bottom
CI48  68P_0402_50V8J  [C_0402]  86.95 102.71 180 bottom
CI50  100P_0402_50V8J  [C_0402]  84.48 104.74 225 bottom
CI51  27P_0402_50V8J  [C_0402]  85.11 104.1 225 bottom
CI52  18P_0402_50V8J  [C_0402]  87.66 104.74 0 bottom
CI801  100U_A_6.3VM_R70M  [C_A]  88.28 102.02 0 bottom
CL1  0.1U_0402_25V6  [C_0402]  275.28 79.51 90 top
CL2  0.1U_0402_25V6  [C_0402]  276.17 79.51 90 top
CL3  0.1U_0201_10V6K  [C_0201]  285.96 86.57 270 top
CL4  10U_0603_10V6M  [C_0603]  286.9 87.14 270 top
CL5  0.1U_0402_25V6  [C_0402]  277.31 79.57 90 top
CL6  0.1U_0402_25V6  [C_0402]  278.2 79.51 90 top
CL7  0.1U_0201_10V6K  [C_0201]  279.53 88.96 270 bottom
CL8  0.1U_0201_10V6K  [C_0201]  274.45 80.57 270 top
CL9  0.1U_0201_10V6K  [C_0201]  276.23 82.53 90 bottom
CL10  0.1U_0201_10V6K  [C_0201]  276.99 82.53 90 bottom
CL11  0.1U_0201_10V6K  [C_0201]  278.77 88.96 270 bottom
CL12  22U_0603_6.3V6M  [C_0603]  279.47 82.57 180 bottom
CL13  27P_0402_50V8J  [C_0402]  286.39 89.38 270 top
CL14  27P_0402_50V8J  [C_0402]  284.36 89.35 90 top
CL15  0.1U_0201_10V6K  [C_0201]  270.64 89.39 90 top
CL16  0.1U_0201_10V6K  [C_0201]  301.63 92.69 90 top
CL17  0.1U_0201_10V6K  [C_0201]  298.58 92.69 90 top
CL18  470P_0402_50V7K  [C_0402]  277.51 104.03 180 top
CL19  0.1U_0201_10V6K  [C_0201]  304.68 96.79 180 top
CL20  0.1U_0201_10V6K  [C_0201]  296.17 92.69 90 top
CL21  0.1U_0201_10V6K  [C_0201]  292.74 92.69 90 top
CL22  10P_1808_3KV8J  [C_1808]  285.88 94.74 90 bottom
CL28  22U_0805_6.3V6M  [C_0805]  283.34 83.58 0 top
CL29  12P_0402_50V8J  [C_0402]  274.83 86.25 0 bottom
CL30  82P_0402_50V8J  [C_0402]  278.01 88.87 270 bottom
CLIP1  -  [CLIP_SH1506X616]  244.25 31.25 0 top
CMOS1  SHORT PADS~D  [SHORTPADS-NPM]  152.37 51.89 270 bottom
CN1  10U_0603_10V6M  [C_0603]  273.37 42.31 180 bottom
CN2  0.1U_0201_10V6K  [C_0201]  274.41 42.31 0 bottom
CN3  0.1U_0201_10V6K  [C_0201]  274.55 46.38 0 bottom
CN4  0.01UF_0402_25V7K  [C_0402]  270.64 36.9 90 bottom
CN5  0.01UF_0402_25V7K  [C_0402]  271.66 36.9 90 bottom
CN6  0.01UF_0402_25V7K  [C_0402]  272.67 36.9 90 bottom
CN7  0.01UF_0402_25V7K  [C_0402]  273.69 36.9 90 bottom
CN8  1000P_0402_50V7K  [C_0402]  280.34 36.72 0 bottom
CN9  0.1U_0201_10V6K  [C_0201]  278.68 36.72 180 bottom
CN10  0.1U_0201_10V6K  [C_0201]  275.08 37.58 180 bottom
CN11  0.1U_0201_10V6K  [C_0201]  275.08 36.82 180 bottom
CN12  0.01UF_0402_25V7K  [C_0402]  280.55 68.29 270 top
CN13  0.01UF_0402_25V7K  [C_0402]  279.6 68.29 270 top
CN14  0.01UF_0402_25V7K  [C_0402]  278.64 68.29 270 top
CN15  0.01UF_0402_25V7K  [C_0402]  277.69 68.29 270 top
CN16  0.01UF_0402_25V7K  [C_0402]  280.66 65.44 0 top
CN17  0.1U_0201_10V6K  [C_0201]  272.84 61.93 180 top
CN20  0.1U_0201_10V6K  [C_0201]  260.96 50.25 180 top
CN21  0.01UF_0402_25V7K  [C_0402]  260.88 51.01 180 top
CN22  0.22U_0402_10V6K  [C_0402]  258.37 48.53 0 top
CN23  0.22U_0402_10V6K  [C_0402]  258.37 47.52 0 top
CN26  0.22U_0402_10V6K  [C_0402]  258.63 45.48 0 top
CN27  0.22U_0402_10V6K  [C_0402]  258.63 46.5 0 top
CN30  0.1U_0201_10V6K  [C_0201]  287.91 54.5 0 bottom
CN31  0.01UF_0402_25V7K  [C_0402]  294.26 58.44 0 top
CN32  0.22U_0402_10V6K  [C_0402]  286.38 52.57 0 bottom
CN33  0.22U_0402_10V6K  [C_0402]  286.38 51.67 0 bottom
CN36  0.22U_0402_10V6K  [C_0402]  290.9 51.58 90 bottom
CN37  0.22U_0402_10V6K  [C_0402]  290.01 51.58 90 bottom
CN60  68P_0402_50V8J  [C_0402]  306.14 27.77 180 top
CN61  0.1U_0201_10V6K  [C_0201]  290.11 27.64 180 top
CN62  0.1U_0201_10V6K  [C_0201]  304.53 27.6 90 top
CN63  22U_0603_6.3V6M  [C_0603]  291.03 28.85 0 top
CN64  22U_0603_6.3V6M  [C_0603]  291.03 30.05 0 top
CN69  0.22U_0402_10V6K  [C_0402]  283.48 39.64 180 bottom
CN70  0.22U_0402_10V6K  [C_0402]  283.48 38.75 180 bottom
CN71  0.22U_0402_10V6K  [C_0402]  283.48 37.61 180 bottom
CN72  0.22U_0402_10V6K  [C_0402]  283.48 36.72 180 bottom
CR1  4.7U_0402_6.3V6M  [C_0402]  24.26 46.2 270 top
CR2  0.1U_0201_10V6K  [C_0201]  25.02 45.87 270 top
CR3  0.1U_0201_10V6K  [C_0201]  27.52 54.28 0 top
CR4  10U_0402_6.3V6M  [C_0402]  26.68 54.32 90 top
CR5  4.7U_0603_6.3V6K  [C_0603]  25.41 55.33 180 top
CR6  0.1U_0201_10V6K  [C_0201]  25.21 54.13 0 top
CR7  0.1U_0201_10V6K  [C_0201]  28.71 54.01 90 top
CR11  0.1U_0402_25V6  [C_0402]  31.39 49.1 180 top
CR12  0.1U_0402_25V6  [C_0402]  31.39 49.99 180 top
CR13  0.1U_0402_25V6  [C_0402]  31.39 50.93 180 top
CR14  0.1U_0402_25V6  [C_0402]  31.39 51.82 180 top
CR17  0.1U_0201_10V6K  [C_0201]  31.88 43.48 90 top
CR18  4.7U_0603_6.3V6K  [C_0603]  31.88 47.07 270 top
CR19  0.1U_0201_10V6K  [C_0201]  6.74 59.86 90 top
CR20  4.7U_0603_6.3V6K  [C_0603]  7.69 59.52 90 top
CR21  5P_0402_50V8C  [C_0402]  20.81 53.74 270 top
CR25  12P_0402_50V8J  [C_0402]  21.83 43.08 270 top
CR26  82P_0402_50V8J  [C_0402]  20.82 43.08 270 top
CR27  12P_0402_50V8J  [C_0402]  23.25 46.2 270 top
CR28  82P_0402_50V8J  [C_0402]  22.23 46.2 270 top
CR1501  1U_0201_6.3V6M  [C_0201]  21.25 47.95 180 top
CR1502  1U_0201_6.3V6M  [C_0201]  21.25 47.36 180 top
CR2201  1U_0201_6.3V6M  [C_0201]  21.54 51.49 90 top
CR2202  1U_0201_6.3V6M  [C_0201]  20.96 51.49 90 top
CT70  .1U_0402_16V7K  [C_0402]  33.91 99.13 90 bottom
CT71  2.2U_0402_16V6K  [C_0402]  33.53 84.65 90 top
CT72  2.2U_0402_16V6K  [C_0402]  37.46 84.6 0 top
CT73  2.2U_0402_16V6K  [C_0402]  26.81 84.85 180 top
CT74  1U_0402_10V6K  [C_0402]  30.92 86 0 top
CT75  22U_0805_25V6M  [C_0805]  41.84 92.01 270 top
CT76  22U_0805_25V6M  [C_0805]  45.68 92.04 270 top
CT77  22U_0805_25V6M  [C_0805]  43.81 92 270 top
CT78  22U_0805_25V6M  [C_0805]  45.7 92.04 270 bottom
CT80  0.1U_0201_10V6K  [C_0201]  29.09 87.37 270 top
CT81  0.1U_0201_10V6K  [C_0201]  28.33 87.37 270 top
CT82  1U_0603_25V6K  [C_0603]  37.15 76.15 0 top
CT83  1U_0402_10V6K  [C_0402]  29.07 84.21 270 bottom
CT84  10U_0603_6.3V6M  [C_0603]  40.39 85.87 90 top
CT85  820P_0402_50V7K  [C_0402]  28.28 75.47 270 top
CT86  820P_0402_50V7K  [C_0402]  25.86 77.55 180 top
CT87  0.22U_0402_16V7K  [C_0402]  30.36 79.53 270 bottom
CT88  0.1U_0201_10V6K  [C_0201]  40.73 97.3 0 bottom
CT89  1U_0402_10V6K  [C_0402]  40.57 96.28 0 bottom
CT90  1U_0402_10V6K  [C_0402]  39.5 100.81 270 bottom
CT91  2.2U_0402_10V6M  [C_0402]  44.84 99.17 90 bottom
CT92  0.1U_0402_25V6K  [C_0402]  43.26 97.05 180 bottom
CT93  1U_0402_10V6K  [C_0402]  24.2 89.88 270 bottom
CT94  1U_0603_50V6K  [C_0603]  17.72 84.35 270 bottom
CT95  0.22U_0201_6.3V6K  [C_0201]  13.22 94.24 180 bottom
CT96  0.22U_0201_6.3V6K  [C_0201]  13.22 95 180 bottom
CT97  0.22U_0201_6.3V6K  [C_0201]  13.22 100.84 180 top
CT98  0.22U_0201_6.3V6K  [C_0201]  13.22 100.03 180 top
CT99  0.01U_0201_25V6K  [C_0201]  8.34 95.58 270 top
CT100  0.01U_0201_25V6K  [C_0201]  8.92 95.58 270 top
CT101  0.01U_0201_25V6K  [C_0201]  8.26 98.02 90 top
CT102  0.01U_0201_25V6K  [C_0201]  7.63 98.02 90 top
CT103  0.1U_0402_25V6  [C_0402]  26.24 98.57 180 bottom
CT104  0.1U_0402_25V6  [C_0402]  26.24 97.55 180 bottom
CT105  0.1U_0402_25V6  [C_0402]  26.24 96.54 180 bottom
CT106  0.1U_0402_25V6  [C_0402]  26.24 95.52 180 bottom
CT107  0.1U_0402_25V6  [C_0402]  26.24 94.51 180 bottom
CT108  0.1U_0402_25V6  [C_0402]  26.24 93.49 180 bottom
CT109  0.1U_0402_25V6  [C_0402]  26.24 92.47 180 bottom
CT110  0.1U_0402_25V6  [C_0402]  26.24 91.46 180 bottom
CT111  0.1U_0402_25V6  [C_0402]  22.48 100.81 270 bottom
CT112  0.1U_0402_25V6  [C_0402]  21.47 100.81 270 bottom
CT113  0.1U_0402_25V6  [C_0402]  24.52 100.81 270 bottom
CT114  0.1U_0402_25V6  [C_0402]  23.5 100.81 270 bottom
CT115  0.1U_0402_25V6  [C_0402]  22.36 88.84 90 bottom
CT116  0.1U_0402_25V6  [C_0402]  21.47 88.84 90 bottom
CT117  10U_0402_6.3V6M  [C_0402]  21.98 97.76 270 top
CT118  0.1U_0201_10V6K  [C_0201]  20.45 91.42 90 top
CT119  0.1U_0201_10V6K  [C_0201]  21 97.81 180 top
CT120  0.1U_0201_10V6K  [C_0201]  19.69 91.42 90 top
CT121  0.1U_0201_10V6K  [C_0201]  23.53 92.69 90 top
CT122  2.2U_0402_6.3V6M  [C_0402]  17.85 99.89 90 bottom
CT189  12P_0402_50V8J  [C_0402]  9.02 98.11 90 top
CT190  82P_0402_50V8J  [C_0402]  9.66 95.47 270 top
CT213  0.1U_0402_25V6  [C_0402]  25.35 92.98 0 top
CV1  0.1U_0402_25V6  [C_0402]  98.3 87.89 90 bottom
CV2  0.1U_0402_25V6  [C_0402]  97.41 87.89 90 bottom
CV3  0.1U_0402_25V6  [C_0402]  96.53 87.89 90 bottom
CV4  0.1U_0402_25V6  [C_0402]  95.64 87.89 90 bottom
CV5  0.1U_0402_25V6  [C_0402]  94.75 87.89 90 bottom
CV6  0.1U_0402_25V6  [C_0402]  93.86 87.89 90 bottom
CV11  100P_0402_50V8J  [C_0402]  109.91 86.45 180 bottom
CV12  0.1U_0201_10V6K  [C_0201]  102.27 88.98 0 bottom
CV13  1000P_0402_50V7K  [C_0402]  106.53 81.79 90 bottom
CV14  0.01U_0402_50V7K  [C_0402]  104.53 81.79 90 bottom
CV15  0.1U_0603_50V7K  [C_0603]  108.58 85.15 0 bottom
CV16  100P_0402_50V8J  [C_0402]  98.76 86.25 0 bottom
CV17  0.01UF_0402_25V7K  [C_0402]  97.29 85.35 90 bottom
CV18  12P_0402_50V8J  [C_0402]  121.16 88.8 270 bottom
CV19  82P_0402_50V8J  [C_0402]  122.18 88.8 270 bottom
CV20  12P_0402_50V8J  [C_0402]  101.1 86.25 0 bottom
CV21  82P_0402_50V8J  [C_0402]  101.97 88.22 0 bottom
CV22  12P_0402_50V8J  [C_0402]  111.82 88.09 0 bottom
CV23  82P_0402_50V8J  [C_0402]  111.82 87.1 0 bottom
CV24  12P_0402_50V8J  [C_0402]  108.46 88.79 0 bottom
CV25  82P_0402_50V8J  [C_0402]  108.46 87.9 0 bottom
CV31  0.1U_0402_25V6  [C_0402]  98.11 101.29 90 top
CV32  0.1U_0402_25V6  [C_0402]  99 101.29 90 top
CV33  0.1U_0402_25V6  [C_0402]  101.67 101.29 90 top
CV34  0.1U_0402_25V6  [C_0402]  102.56 101.29 90 top
CV35  0.1U_0402_25V6  [C_0402]  108.34 100.21 90 top
CV36  0.1U_0402_25V6  [C_0402]  109.35 100.21 90 top
CV37  0.1U_0402_25V6  [C_0402]  105.35 102.14 270 top
CV38  0.1U_0402_25V6  [C_0402]  106.24 102.14 270 top
CV39  0.1U_0201_10V6K  [C_0201]  116.11 105.24 0 top
CV40  0.1U_0201_10V6K  [C_0201]  112.19 108.17 90 top
CV41  10U_0603_10V6M  [C_0603]  113.13 108.3 90 top
CV81  0.01UF_0402_25V7K  [C_0402]  96.33 99.32 90 top
CV82  0.01UF_0402_25V7K  [C_0402]  106.57 99.41 180 top
CV83  0.1U_0201_10V6K  [C_0201]  107.32 99.17 90 top
CV84  0.1U_0201_10V6K  [C_0201]  107.85 93.68 0 top
CV85  0.1U_0201_10V6K  [C_0201]  99.51 89.97 270 top
CV86  0.1U_0201_10V6K  [C_0201]  100.27 89.32 90 top
CV87  0.1U_0201_10V6K  [C_0201]  100.91 89.32 90 top
CV88  0.1U_0201_10V6K  [C_0201]  101.73 89.32 90 top
CV89  0.1U_0201_10V6K  [C_0201]  102.37 89.32 90 top
CV90  0.1U_0201_10V6K  [C_0201]  103 89.32 90 top
CV91  0.1U_0201_10V6K  [C_0201]  103.64 89.32 90 top
CV92  0.1U_0201_10V6K  [C_0201]  104.27 89.32 90 top
CV93  0.1U_0201_10V6K  [C_0201]  104.91 89.32 90 top
CV94  0.1U_0201_10V6K  [C_0201]  108.44 94.7 180 top
CV95  0.1U_0201_10V6K  [C_0201]  108.44 95.27 180 top
CV96  2.2U_0402_6.3V6M  [C_0402]  106.05 90.96 270 top
CV100  0.1U_0402_25V6  [C_0402]  282.78 56.15 180 top
CV101  0.1U_0402_25V6  [C_0402]  282.19 53.42 0 top
CV102  4.7U_0402_6.3V6M  [C_0402]  282.19 54.37 0 top
CV103  0.1U_0402_25V6  [C_0402]  273.51 56.34 180 bottom
CV104  0.1U_0402_25V6  [C_0402]  278.69 59.5 0 bottom
CV105  2.2U_0402_16V6K  [C_0402]  278.69 58.62 0 bottom
CV106  0.1U_0402_25V6  [C_0402]  277.88 57.3 270 bottom
CV107  0.1U_0402_10V7K  [C_0402]  272.6 55.45 0 bottom
CV108  0.1U_0402_10V7K  [C_0402]  272.6 54.56 0 bottom
CV109  0.1U_0402_10V7K  [C_0402]  272.6 53.67 0 bottom
CV110  0.1U_0402_10V7K  [C_0402]  272.6 52.78 0 bottom
CV111  0.1U_0402_10V7K  [C_0402]  272.85 58.44 0 bottom
CV112  0.1U_0402_10V7K  [C_0402]  272.85 57.55 0 bottom
CV126  12P_0402_50V8J  [C_0402]  317.4 90.43 90 bottom
CV127  12P_0402_50V8J  [C_0402]  316.08 90.43 90 bottom
CV128  12P_0402_50V8J  [C_0402]  313.44 75.34 270 bottom
CV129  3.3P_0402_50V8C  [C_0402]  317.43 87.58 0 bottom
CV130  3.3P_0402_50V8C  [C_0402]  316.06 87.58 180 bottom
CV131  3.3P_0402_50V8C  [C_0402]  313.52 77.93 180 bottom
CV132  2P_0402_50V8C~D  [C_0402]  317.63 76.36 270 top
CV133  2P_0402_50V8C~D  [C_0402]  317.63 78.64 270 top
CV134  1U_0402_6.3V6K  [C_0402]  318.39 77.12 270 bottom
CV135  0.1U_0402_16V4Z  [C_0402]  318.39 75.09 270 bottom
CV635  0.1U_0402_25V6K  [C_0402]  127.69 91.13 180 bottom
CZ1  100P_0201_25V7K  [C_0201]  111.85 88.85 0 bottom
CZ2  0.1U_0201_10V6K  [C_0201]  120.4 88.89 270 bottom
CZ3  100P_0402_50V8J  [C_0402]  80.9 96.54 0 bottom
CZ10  0.1U_0402_25V6  [C_0402]  292.28 65.61 0 bottom
CZ11  0.1U_0402_25V6  [C_0402]  292.28 66.57 0 bottom
CZ12  0.1U_0402_25V6  [C_0402]  196.72 16.78 0 bottom
CZ13  0.1U_0402_25V6  [C_0402]  196.72 15.77 0 bottom
CZ17  .047U_0402_16V7K  [C_0402]  282.62 47.58 90 bottom
CZ18  .047U_0402_16V7K  [C_0402]  283.51 47.58 90 bottom
CZ19  33P_0402_50V8J  [C_0402]  303.66 47.02 270 top
CZ20  22U_0603_6.3V6M  [C_0603]  282.47 46.68 270 bottom
CZ21  33P_0402_50V8J  [C_0402]  303.13 48.89 90 top
CZ23  47P_0402_50V8J  [C_0402]  304.02 48.89 90 top
CZ24  100P_0402_50V8J  [C_0402]  304.91 48.89 90 top
CZ25  2000P_0402_50V7K  [C_0402]  304.55 47.02 270 top
CZ26  100U_B2_6.3VM_R35M  [C_B2]  309.5 47.24 90 bottom
CZ27  10U_0603_10V6M  [C_0603]  214.89 6.43 0 top
CZ28  0.01UF_0402_25V7K  [C_0402]  207.14 30.8 90 bottom
CZ29  0.01UF_0402_25V7K  [C_0402]  214.76 5.3 270 top
CZ30  0.1U_0201_10V6K  [C_0201]  214.85 7.38 0 top
CZ31  0.1U_0201_10V6K  [C_0201]  206.93 27.96 180 bottom
CZ32  4.7U_0603_6.3V6K  [C_0603]  205.87 30.82 90 bottom
CZ33  15P_0402_50V8J  [C_0402]  207.09 28.72 180 bottom
CZ34  15P_0402_50V8J  [C_0402]  207.09 29.67 180 bottom
CZ35  15P_0402_50V8J  [C_0402]  214.81 8.15 0 top
CZ36  15P_0402_50V8J  [C_0402]  215.78 5.3 270 top
CZ37  4.7U_0402_6.3V6M  [C_0402]  117.78 112.41 0 bottom
CZ38  47P_0402_50V8J  [C_0402]  118.69 109.76 270 bottom
CZ39  33P_0402_50V8J  [C_0402]  118.69 110.62 90 bottom
CZ40  33P_0402_50V8J  [C_0402]  132.47 100.22 0 bottom
CZ41  0.1U_0402_25V6  [C_0402]  125.53 102.66 270 top
CZ50  0.1U_0201_10V6K  [C_0201]  170.82 39.48 90 top
CZ51  0.1U_0201_10V6K  [C_0201]  170.12 33.67 180 top
CZ52  10U_0603_10V6M  [C_0603]  170.19 32.72 180 top
CZ53  0.1U_0201_10V6K  [C_0201]  163.01 36.19 270 top
CZ54  0.1U_0201_10V6K  [C_0201]  166.31 41.51 90 top
CZ55  10U_0603_10V6M  [C_0603]  168.98 41.93 90 top
CZ56  0.1U_0402_25V6  [C_0402]  158.89 38.94 180 top
CZ57  12P_0402_50V8J  [C_0402]  182.05 32.66 0 top
CZ58  68P_0402_50V8J  [C_0402]  182.05 31.73 0 top
CZ59  12P_0402_50V8J  [C_0402]  171.39 42.93 90 top
CZ60  68P_0402_50V8J  [C_0402]  172.34 42.93 90 top
CZ61  .047U_0402_16V7K  [C_0402]  219.14 19.53 270 top
CZ62  100P_0402_50V8J  [C_0402]  221.06 10.43 180 top
CZ63  100P_0402_50V8J  [C_0402]  221.06 11.7 180 top
CZ64  27P_0402_50V8J  [C_0402]  221.04 14.67 270 top
CZ66  0.1U_0201_10V6K  [C_0201]  220.99 17.93 90 top
CZ67  27P_0402_50V8J  [C_0402]  221.04 16.43 270 top
CZ68  27P_0402_50V8J  [C_0402]  220.17 12.62 180 top
CZ69  100P_0402_50V8J  [C_0402]  220.17 14.47 180 top
CZ71  68P_0402_50V8J  [C_0402]  220.1 17.8 90 top
CZ72  100P_0402_50V8J  [C_0402]  220.15 15.82 180 top
CZ73  100P_0402_50V8J  [C_0402]  220.17 13.51 180 top
CZ75  10U_0402_6.3V6M  [C_0402]  171.58 39.44 90 top
CZ80  10P_0402_50V8J  [C_0402]  215.83 26.18 0 top
CZ81  10P_0402_50V8J  [C_0402]  215.83 23.13 0 top
CZ82  0.1U_0201_10V6K  [C_0201]  138.05 30.75 0 top
CZ83  68P_0402_50V8J  [C_0402]  215.73 18.54 270 top
